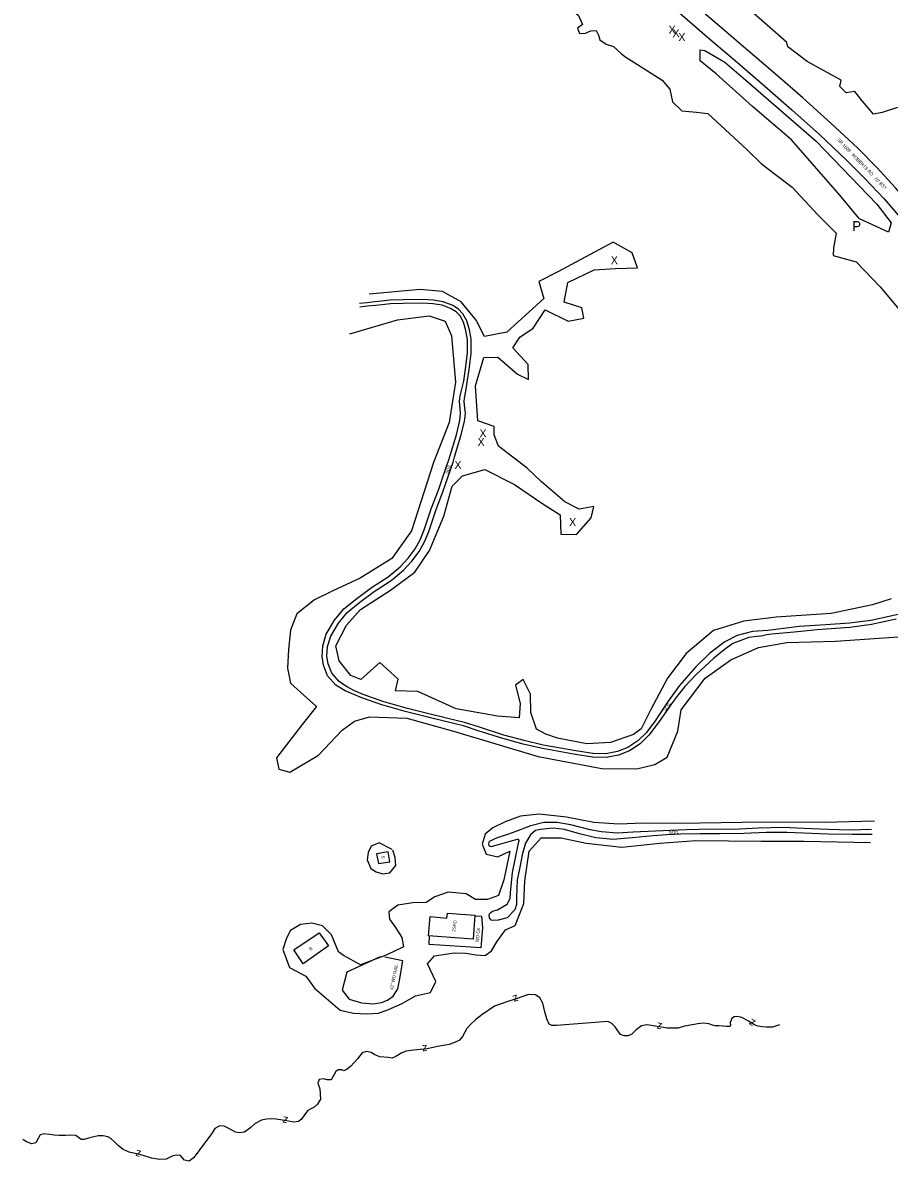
# Model space of a CAD drawing. Extents: x 2030130 to 2036320, y 723205 to 762423.
# Drawn here: x 2032607 to 2033690, y 732880 to 734303 of the extents above; entities that cross this region are included whole.
import ezdxf

# ---------------------------------------------------------------- set-up
doc = ezdxf.new("R2010")
doc.units = 0
for name, color, linetype in [('Draft_Station Labels Major', 7, 'Continuous'), ('Draft_Station Tics Major', 7, 'Continuous'), ('Exist Terrain Model Ground Surface', 7, 'Continuous'), ('Old_Level_23', 7, 'Continuous'), ('Old_Level_28', 7, 'Continuous'), ('Prop Alignment Horizontal', 7, 'Continuous'), ('Prop Horizontal Alignment Ramp', 7, 'Continuous')]:
    doc.layers.add(name, color=color, linetype=linetype)

msp = doc.modelspace()

# ---------------------------------------------------------------- linework, layer by layer
at = {"layer": 'Draft_Station Labels Major'}
for points in [[(2033650.8, 734146.7), (2033617.2, 734178), (2033582.2, 734209.3), (2033547.5, 734239.3), (2033513.4, 734268.8), (2033478.5, 734298.7), (2033443.8, 734328.4), (2033408, 734359), (2033373, 734389), (2033337.5, 734419.8)], [(2033323.5, 734405.1), (2033360.4, 734373.3), (2033395.1, 734343.7), (2033431.2, 734313), (2033465.6, 734283.4), (2033500.4, 734253.6), (2033534.6, 734224), (2033568.5, 734194.3), (2033602.8, 734163.7), (2033636.3, 734131.9), (2033659.9, 734108.3), (2033683.5, 734083.1), (2033706.2, 734056.8), (2033727.1, 734030.7), (2033748, 734002.9), (2033774.8, 733965.5)], [(2033792, 733977), (2033764.1, 734015.1), (2033743.3, 734042.9), (2033721.2, 734070.2), (2033698, 734097), (2033674.5, 734122.4), (2033650.8, 734146.7)], [(2033527.4, 733536.8), (2033514.4, 733535.1), (2033494.8, 733527.4), (2033483.6, 733519.7), (2033470.6, 733508.8), (2033449, 733489), (2033434.8, 733473.7), (2033426.1, 733463.4), (2033418.8, 733453.3), (2033404.5, 733432.7), (2033390.2, 733413.2), (2033378.6, 733402.2), (2033365.4, 733393.3), (2033351.9, 733387.9), (2033336.4, 733385.1), (2033319.1, 733385.4), (2033297.8, 733388.7), (2033256.9, 733396.1), (2033232.6, 733401.6), (2033207.2, 733408.6), (2033176.5, 733418.4), (2033158.2, 733424.5), (2033137.4, 733429.5), (2033111.9, 733435.7), (2033085.2, 733442.3), (2033055.9, 733450.6), (2033031.1, 733459.6), (2033010.3, 733468.1), (2032998.6, 733475.3), (2032988.3, 733487.1), (2032983, 733500.5), (2032981.3, 733511.2), (2032982.1, 733524.7), (2032986.6, 733539), (2032997, 733556.4), (2033008.5, 733570.6), (2033024.8, 733583.6), (2033043.1, 733597.4), (2033064, 733610.8), (2033079.1, 733623.2), (2033088.8, 733634), (2033097.8, 733645.8), (2033104.1, 733656.9), (2033109, 733669.6), (2033117.7, 733695.9), (2033127.2, 733720.3), (2033135.7, 733745.3), (2033139.3, 733755.7), (2033141.2, 733762.4), (2033149.1, 733788.3), (2033153.4, 733806), (2033154.4, 733815.1), (2033153.8, 733821.2), (2033152.9, 733829.8), (2033153.7, 733836.8), (2033158.4, 733855.4), (2033160.7, 733870.6), (2033163.1, 733890.4), (2033163.1, 733907.5), (2033161.1, 733918.5), (2033158, 733929.1), (2033153.7, 733936.8), (2033148.7, 733942.1), (2033141.7, 733946.2), (2033131.3, 733950.2), (2033119.8, 733951.9), (2033106.7, 733952.7), (2033082.7, 733952.3), (2033066.7, 733952), (2033055.9, 733950.8), (2033047.9, 733949.9), (2033038.2, 733948.9), (2033028.5, 733947.9)], [(2033163.1, 733856.4), (2033165.2, 733870), (2033167.7, 733890.1), (2033167.6, 733907.9), (2033165.5, 733919.5), (2033162.2, 733930.9), (2033157.4, 733939.5), (2033151.5, 733945.6), (2033143.7, 733950.3), (2033132.5, 733954.6), (2033120.2, 733956.4), (2033106.8, 733957.3), (2033082.6, 733956.8), (2033066.4, 733956.6), (2033055.4, 733955.3), (2033047.4, 733954.4), (2033037.7, 733953.4), (2033028.1, 733952.4)], [(2033159.4, 733834.1), (2033160.8, 733842.8), (2033163.1, 733856.4)], [(2033006.2, 733477.6), (2033002.5, 733479.9), (2032993.4, 733490.3), (2032988.8, 733502.1), (2032987.3, 733511.5), (2032988, 733523.6), (2032992.1, 733536.6), (2033001.9, 733553), (2033012.7, 733566.3), (2033028.4, 733578.9), (2033046.4, 733592.5), (2033067.5, 733606), (2033083.2, 733618.9), (2033093.4, 733630.2), (2033102.8, 733642.6), (2033109.4, 733654.4), (2033114.6, 733667.6), (2033123.3, 733693.8), (2033132.8, 733718.2), (2033141.4, 733743.3), (2033145, 733753.9), (2033146.9, 733760.7), (2033154.9, 733786.8), (2033159.3, 733805), (2033160.4, 733815.1), (2033159.7, 733821.9), (2033158.8, 733829.8), (2033159.4, 733834.1)], [(2033864.6, 733659.4), (2033863.4, 733657.5), (2033854.4, 733640.7), (2033846.8, 733627), (2033838.9, 733616.5), (2033833.7, 733610.4), (2033826.8, 733604.5), (2033817, 733597.9), (2033808.2, 733593.3), (2033797.5, 733588.6), (2033783.9, 733583.8), (2033768.2, 733579.3), (2033750.9, 733574.4), (2033728.7, 733569.8), (2033697.5, 733562.9), (2033667, 733556.3), (2033640.2, 733552.7), (2033610.7, 733550.6)], [(2033610.7, 733550.6), (2033577.3, 733548.5), (2033538.2, 733543.8), (2033519.1, 733542.3), (2033500, 733537.3), (2033484.5, 733529.5), (2033466, 733515.4), (2033448.2, 733498.3), (2033428, 733474.8), (2033413.7, 733455.5), (2033397.4, 733430.7)], [(2033698.7, 733557.7), (2033667.9, 733551.1), (2033640.7, 733547.3), (2033599.8, 733544.5), (2033571.1, 733541.8), (2033543.3, 733538.9), (2033534.3, 733537.7)], [(2033527.4, 733536.8), (2033534.3, 733537.7)], [(2033021.2, 733468.5), (2033012.7, 733473.2), (2033006.2, 733477.6)], [(2033397.4, 733430.7), (2033386.8, 733416.2), (2033375.8, 733405.7), (2033363.3, 733397.3), (2033350.6, 733392.3), (2033336, 733389.6), (2033319.5, 733390), (2033298.5, 733393.2), (2033257.8, 733400.5), (2033233.7, 733406), (2033208.5, 733413), (2033177.9, 733422.7), (2033159.4, 733428.9), (2033138.5, 733433.9), (2033113, 733440.1), (2033086.3, 733446.6), (2033057.3, 733454.9), (2033032.7, 733463.8), (2033021.2, 733468.5)], [(2033200.7, 733194.5), (2033212.6, 733201.6), (2033216.4, 733208.9), (2033216.7, 733215.8), (2033219.4, 733241.4), (2033223.3, 733261.8), (2033226.5, 733275.9), (2033227.7, 733281), (2033226.9, 733282.3), (2033225.3, 733282.4), (2033215.9, 733280.1), (2033201.4, 733275.6), (2033192.3, 733273.1), (2033190, 733274.4), (2033189.5, 733277), (2033190.5, 733280.3), (2033200.6, 733284.8), (2033214.7, 733289.6), (2033227, 733294.1), (2033242.3, 733299.8), (2033258.5, 733304.2), (2033275.1, 733304.2), (2033291.6, 733301.3), (2033315.9, 733294.9), (2033330.4, 733292.3), (2033350, 733290.8), (2033370.2, 733291.9), (2033416.8, 733294.2), (2033436.5, 733295.1), (2033466.7, 733295.6), (2033495.1, 733295.5), (2033526.8, 733297.2), (2033557.6, 733297.8), (2033583.4, 733296.7), (2033614.2, 733295.5), (2033640.8, 733294.7), (2033667.9, 733295.5)], [(2033668.9, 733288.8), (2033644.2, 733288.8), (2033613.8, 733289), (2033582.7, 733290.3), (2033562.2, 733291.2), (2033536.3, 733291), (2033508.2, 733290.1), (2033478.3, 733289.7), (2033453.2, 733289.5), (2033429.7, 733289.3), (2033412.1, 733288.2), (2033395, 733287.1), (2033368.9, 733284.7), (2033344.7, 733282.6), (2033332.6, 733283.5), (2033323.3, 733284.7), (2033303, 733289.7), (2033284.1, 733294.8), (2033270.3, 733296.7), (2033254.1, 733295.1), (2033248.1, 733293.5), (2033241.9, 733288.1), (2033235.7, 733277.8), (2033231.5, 733263.2), (2033229.2, 733251.9), (2033225.2, 733231.7), (2033224.3, 733209.9), (2033224.4, 733201.2), (2033222.3, 733194.6), (2033212.7, 733184.7), (2033201.5, 733181.8)], [(2033201.5, 733181.8), (2033194.7, 733181.1), (2033192.7, 733181.8), (2033190.7, 733184.6), (2033190.1, 733187.5), (2033190.4, 733189.7), (2033192.1, 733191.4), (2033194.4, 733192.8), (2033200.7, 733194.5)]]:
    msp.add_lwpolyline(points, dxfattribs=at)
at = {"layer": 'Draft_Station Tics Major'}
msp.add_line((2033688.9, 734041.6), (2033653, 734058.3), dxfattribs=at)
for points in [[(2033224.4, 734382.4), (2033241.5, 734365.7), (2033248, 734361.9), (2033251.5, 734355.1), (2033255.6, 734348.1), (2033270, 734335), (2033277.5, 734331.8), (2033285.7, 734323.9), (2033294.9, 734318.4), (2033301.7, 734312.4), (2033306.6, 734301.2), (2033300.7, 734296.6), (2033302.9, 734290), (2033310.5, 734290.1), (2033317.2, 734293.2), (2033323.7, 734293.7), (2033326.7, 734287.7), (2033328.3, 734281.8), (2033336.2, 734276.5), (2033345.6, 734273.5), (2033354.9, 734264.9), (2033359.7, 734261.1)], [(2033587.5, 734254.7), (2033563.3, 734273.4), (2033562, 734278.7), (2033537.5, 734300.2), (2033504.3, 734329.5)], [(2033652.4, 734058.6), (2033628.4, 734087.8), (2033568, 734157), (2033519.1, 734198.8), (2033473.6, 734239.5), (2033453.8, 734255.6), (2033453.9, 734269.4), (2033459.7, 734268.7), (2033484.5, 734253.9)], [(2033359.7, 734261.1), (2033387.8, 734243.4), (2033406.5, 734231.7), (2033415.7, 734220.2), (2033419.4, 734204.6), (2033430.7, 734193.1), (2033449.4, 734191.4), (2033463.5, 734189.9), (2033512.3, 734144.4), (2033530.5, 734127), (2033568.7, 734097.7), (2033600.9, 734063.2), (2033623.7, 734040.4), (2033620.7, 734024)], [(2033484.5, 734253.9), (2033510.8, 734231.4), (2033598.9, 734155.5), (2033674.5, 734076.5), (2033692.4, 734053.2), (2033689.2, 734041.5)], [(2033752.6, 734248.1), (2033762.2, 734231.6), (2033757, 734222.9), (2033743.5, 734213.8), (2033718, 734201.4), (2033697.9, 734196.5), (2033681.3, 734191.3), (2033670.5, 734188.9), (2033656.3, 734205.9), (2033647.2, 734217.6), (2033636.2, 734215.6), (2033628.5, 734223.5), (2033629.9, 734231.7), (2033587.5, 734254.7)], [(2033692.3, 733583.2), (2033669, 733575.6), (2033617.3, 733565), (2033548.7, 733560.3), (2033508.3, 733555.5), (2033470.4, 733543.8), (2033436.4, 733515.1), (2033413, 733484.1), (2033392.3, 733444.8), (2033380.1, 733420.7), (2033370.6, 733413.7), (2033341.8, 733403.7), (2033312, 733402.1), (2033275.6, 733409), (2033260.8, 733414.1), (2033249.3, 733420.5), (2033242, 733441.4), (2033241.7, 733464.3), (2033232.4, 733482.5), (2033223.1, 733475.4), (2033228.8, 733452.6), (2033227.7, 733434.5), (2033200.6, 733436.7), (2033148.7, 733445.7), (2033100.9, 733467.3), (2033073.1, 733468.2), (2033076.6, 733482.8), (2033053.6, 733503.6), (2033029.7, 733482.4), (2033017.2, 733487.5), (2033002.5, 733505.7), (2032998.7, 733524.4), (2033012, 733550.4), (2033029.2, 733570), (2033067, 733594), (2033097.4, 733616.8), (2033115.4, 733643.8), (2033133.6, 733686.6), (2033143.8, 733724.1), (2033156.9, 733737.1), (2033184.9, 733744.9), (2033221.9, 733726.2), (2033257.2, 733702.1), (2033278.8, 733688.4), (2033279.7, 733664.2), (2033299.2, 733663.7), (2033317.6, 733684.5), (2033320.9, 733698.6), (2033302.5, 733695.4), (2033284.7, 733704.5), (2033255.6, 733729.5), (2033237.5, 733746.5), (2033201.6, 733773.9), (2033196.4, 733788.2), (2033196.3, 733798.5), (2033176.1, 733805.7), (2033173, 733849.5), (2033183.6, 733885.1), (2033201.1, 733885.2), (2033225.4, 733864.2), (2033239.2, 733857.3), (2033239, 733876.2), (2033219.9, 733897.1), (2033228.6, 733910.4), (2033244.9, 733921.5), (2033260, 733944.3), (2033288.7, 733930.4), (2033308.6, 733934.2), (2033305.8, 733946.9), (2033283.9, 733953.9), (2033288.4, 733978.7), (2033321.3, 733994.3), (2033348, 733996.2), (2033375.4, 733997.2), (2033368.6, 734015.8), (2033345, 734029), (2033276.1, 733992.1), (2033252.3, 733980.1), (2033258.5, 733958.8), (2033212, 733916.7)], [(2033620.7, 734024), (2033620.4, 734022.1), (2033620.1, 734012.4), (2033648.9, 734004.5), (2033678.9, 733973.2)], [(2033212, 733916.7), (2033184.3, 733911.2), (2033173.8, 733931.4), (2033155.2, 733954.7), (2033131.7, 733967.6), (2033103.9, 733970), (2033040, 733964.2)], [(2033678.9, 733973.2), (2033736, 733904.6)], [(2033016, 733914.7), (2033075.4, 733931.9), (2033115.3, 733937.2), (2033135, 733930.4), (2033143.1, 733912.2), (2033148, 733854), (2033140.2, 733803.7), (2033120.6, 733753.5), (2033092.9, 733668.1), (2033068.3, 733633.8), (2033029, 733609.3), (2032994.6, 733593.4), (2032972, 733582), (2032949.7, 733564.4), (2032941.9, 733543.9), (2032939.4, 733519.9), (2032938, 733496.6), (2032941.8, 733477.7), (2032954.7, 733466.1), (2032974.5, 733448.8), (2032956.4, 733426.2), (2032924.4, 733384.5), (2032927.5, 733370.5), (2032940.9, 733366.8), (2032977, 733387.8), (2033006.3, 733419.3), (2033022, 733430.2), (2033040.4, 733435.6), (2033087.1, 733434.1), (2033145.6, 733417.9), (2033251.4, 733386.3), (2033330.7, 733371.2), (2033374.5, 733370.9), (2033397.3, 733376), (2033412.7, 733385.3), (2033425.9, 733418), (2033429.9, 733444.5), (2033460, 733484), (2033492.1, 733507), (2033526.5, 733522.6), (2033562, 733528.6), (2033622.8, 733530.5), (2033701.8, 733535.9)], [(2033671.7, 733305.5), (2033608.8, 733303.5), (2033532.8, 733304.3), (2033426.5, 733302.6), (2033383, 733302.7), (2033352.2, 733301.5), (2033321.1, 733303.7), (2033286.6, 733310.4), (2033252.5, 733314.1), (2033229.1, 733311.7), (2033210.2, 733304.4), (2033194.5, 733296.9), (2033185.1, 733289), (2033181.4, 733276.6), (2033186.2, 733264.1), (2033200.9, 733260.6), (2033216, 733268), (2033208.6, 733232.1), (2033201.9, 733212.5), (2033188.1, 733207.5), (2033173.2, 733207.5), (2033161.3, 733214.4), (2033138.8, 733216.6), (2033122.1, 733210.6), (2033111.4, 733203.7)], [(2033199.7, 733154.5), (2033210.7, 733169.4), (2033222.6, 733175), (2033233.6, 733202.6), (2033234.8, 733230.6), (2033240.3, 733267.9), (2033255.1, 733284.5), (2033279.9, 733284.5), (2033311.2, 733277.9), (2033355.7, 733273), (2033403.5, 733277.9), (2033448.2, 733281.1), (2033530.1, 733280.5), (2033583.7, 733280.5), (2033666.5, 733278.5)], [(2033069, 733269.9), (2033052.8, 733278.2), (2033042.8, 733274), (2033038.9, 733266.1), (2033037.8, 733257), (2033042.2, 733246.1), (2033048.8, 733242), (2033057.3, 733239.7), (2033066.2, 733240.9), (2033073.3, 733249.8), (2033072.5, 733260), (2033069.9, 733269)], [(2033111.4, 733203.7), (2033094.6, 733203.5), (2033076, 733200.5), (2033064.7, 733191.9), (2033065.6, 733182.9), (2033073, 733172.5), (2033081, 733159.8), (2033082.9, 733148.1), (2033061.5, 733137.9), (2033029.4, 733125.6), (2033007.9, 733137.6), (2033001.9, 733142.2), (2032993, 733163.1), (2032981.9, 733174.6), (2032968.7, 733177.7), (2032954.4, 733176.4), (2032941.9, 733168.6), (2032936.9, 733159.1), (2032932.1, 733145), (2032940.7, 733122.6), (2032961.2, 733111.7), (2032972, 733096.5), (2033003.9, 733069.3), (2033020.4, 733065.2), (2033037.3, 733064.5), (2033051.7, 733065.4), (2033064.2, 733069.9), (2033081.3, 733077.3), (2033098.2, 733087.2), (2033116.9, 733091.2), (2033123.3, 733104.8), (2033113, 733127), (2033122, 733137.2), (2033146.3, 733140.6), (2033161, 733140.5), (2033173.5, 733138.4), (2033185.2, 733137.5), (2033193.1, 733143.3), (2033199.7, 733154.5)]]:
    msp.add_lwpolyline(points, dxfattribs=at)
at = {"layer": 'Exist Terrain Model Ground Surface'}
for points in [[(2033064, 733267), (2033049.5, 733264.4), (2033051.8, 733252.4), (2033066.2, 733254.6)], [(2033170, 733157.9), (2033114.3, 733162.2), (2033116.5, 733186.3), (2033137.4, 733184), (2033137.9, 733190.4), (2033172.2, 733187.9)], [(2032989.2, 733149.6), (2032957.8, 733127), (2032946.2, 733144.5), (2032977.7, 733165.9)]]:
    msp.add_lwpolyline(points, close=True, dxfattribs=at)
for points in [[(2033172.1, 733187.2), (2033180.4, 733186.7), (2033181.9, 733172.2), (2033179.8, 733147.1), (2033115, 733151.4), (2033115.7, 733162.1)], [(2033053.8, 733135.9), (2033012.3, 733116.8), (2033006.3, 733094.1), (2033015.1, 733083), (2033030.7, 733078.3), (2033045.4, 733077.1), (2033055.4, 733078.9), (2033063.1, 733081.5), (2033070, 733086.8), (2033076.1, 733095.7), (2033078, 733106.4), (2033082.2, 733130.9), (2033059.8, 733135.5)]]:
    msp.add_lwpolyline(points, dxfattribs=at)
at = {"layer": 'Prop Alignment Horizontal'}
for points in [[(2033553, 733050.7), (2033544.1, 733047.8), (2033536.3, 733047.9), (2033531.1, 733048.2), (2033525.9, 733049), (2033521.8, 733050.8), (2033514, 733055.4), (2033508.5, 733058.8), (2033504.4, 733060.5), (2033499.2, 733061.2), (2033496.2, 733061), (2033493.3, 733058.6), (2033491.2, 733053.9), (2033491.8, 733050.5), (2033490.4, 733048.9), (2033486.1, 733048.9), (2033476.9, 733049.6), (2033472.7, 733049.5), (2033469.3, 733050.2), (2033464.7, 733052.2), (2033457.7, 733052.7), (2033451, 733052.2), (2033446.2, 733051.4), (2033434.1, 733049.3), (2033426.2, 733046.7), (2033412.9, 733046.7), (2033387.6, 733050.9), (2033380.3, 733049.7), (2033373.9, 733044.6), (2033368.3, 733039), (2033363.9, 733037.2), (2033359, 733037.1), (2033354.1, 733038.9), (2033350.2, 733044.4), (2033347.6, 733048.5), (2033343.3, 733052.4), (2033338.4, 733054.8), (2033274.4, 733050.1), (2033268.6, 733049.8), (2033264.9, 733051.7), (2033262.3, 733058.3), (2033259.7, 733067), (2033257.1, 733077.8), (2033253.6, 733084.6), (2033247.9, 733088.3), (2033239.4, 733088.6), (2033224, 733083.2), (2033212.3, 733079.6), (2033196.8, 733074.1), (2033181.1, 733063.5), (2033173.5, 733057.4), (2033167.4, 733051.7), (2033162.3, 733046.2), (2033159.8, 733041.8), (2033157, 733036.4), (2033153.1, 733031.5), (2033146, 733028.2), (2033140.1, 733026.3), (2033135.5, 733025.4), (2033125.7, 733023.6), (2033112.7, 733020.9), (2033104.1, 733020), (2033095.5, 733019.1), (2033086.3, 733017.7), (2033081.1, 733015.6), (2033073.5, 733011.1), (2033068.8, 733009), (2033063.8, 733009.8), (2033053.3, 733010.8), (2033047.2, 733013.1), (2033042.8, 733016.1), (2033036.9, 733017.6), (2033031.5, 733015.9), (2033025.7, 733008.1), (2033017.4, 732999.2), (2033012.7, 732995.4), (2033008.6, 732993.4), (2033006, 732994.6), (2033001.3, 732994.7), (2032998.4, 732992.4), (2032992.9, 732982), (2032987.6, 732982), (2032983, 732983.4), (2032977.5, 732982.5), (2032975.9, 732977.9), (2032978.4, 732971), (2032979.3, 732957.9), (2032975.5, 732951.5), (2032971.5, 732947.8), (2032967.3, 732945.9), (2032963.7, 732943.9), (2032959.2, 732938.3), (2032955.8, 732932.9), (2032951.7, 732929.9), (2032946.1, 732929.1), (2032937.2, 732930.7), (2032931.7, 732931.8), (2032923.8, 732933.1), (2032917.7, 732933.2), (2032912, 732933.1), (2032905.5, 732931.7)], [(2032905.5, 732931.7), (2032897.6, 732927.5), (2032892.4, 732922.6), (2032884.2, 732916.7), (2032878, 732915.9), (2032873.3, 732916.8), (2032864.8, 732921.1), (2032859.1, 732924.1), (2032853.5, 732924.4), (2032847.5, 732921.1), (2032843.5, 732914.9), (2032830.5, 732897.9), (2032825.1, 732890.5), (2032820.7, 732884.7), (2032815.1, 732880.3), (2032809.4, 732881.7), (2032804.5, 732887.3), (2032799.2, 732887.9), (2032794, 732886.6), (2032786.5, 732883.1), (2032778.1, 732882.3), (2032768, 732884.3), (2032757.9, 732887.3), (2032753.3, 732888.7), (2032740.2, 732891.6), (2032732.7, 732894.9), (2032726.8, 732899.6), (2032721.4, 732905.1), (2032717.2, 732908.9), (2032713.7, 732910.9), (2032707.7, 732912.1), (2032701.6, 732912.2), (2032694.4, 732910.5), (2032689.6, 732909.1), (2032684, 732907.3), (2032680.3, 732907.4), (2032677.1, 732909.8), (2032673.7, 732912.4), (2032667.5, 732912.8), (2032660.6, 732912.4), (2032653, 732912.6), (2032646.6, 732913.1), (2032640.7, 732913.9), (2032634.7, 732914.7), (2032629.2, 732913.3), (2032623.8, 732903.4), (2032618.8, 732901.9), (2032612.1, 732904.4), (2032608.5, 732906.8), (2032607.4, 732907.8)]]:
    msp.add_lwpolyline(points, dxfattribs=at)

# ---------------------------------------------------------------- texts
at = {"layer": 'Draft_Station Tics Major'}
for p in [(2033414.3, 734289.7), (2033419.2, 734285.3), (2033426.5, 734280.4), (2033342.1, 734001.5), (2033178, 733785.2), (2033175.6, 733774.3), (2033146.7, 733745.7), (2033290, 733674.1)]:
    msp.add_text('X', height=10, dxfattribs=at).set_placement(p)
at = {"layer": 'Old_Level_23'}
for s, rotation, p in [("SR 1608   ROBERTS RD   20' BST", 314.0766, (2033624.6, 734156.4)), ('SOIL', 70.7784, (2033138.8, 733738.9)), ('SOIL', 55.646, (2033410.4, 733442.3)), ('SOIL', 3.8637, (2033414.8, 733289.1))]:
    msp.add_text(s, height=4, rotation=rotation, dxfattribs=at).set_placement(p)
at = {"layer": 'Old_Level_28'}
for s, rotation, p in [('S', 95.5671, (2033059.9, 733258.7)), ('2SFD', 83.4758, (2033147.9, 733167.1)), ('WD DK', 84.1671, (2033177, 733153.9)), ('B', 33.3508, (2032966.8, 733143.3)), ('42" WD RAIL', 78.745, (2033070, 733094.1))]:
    msp.add_text(s, height=4, rotation=rotation, dxfattribs=at).set_placement(p)
at = {"layer": 'Prop Alignment Horizontal'}
for rotation, p in [(198.2017, (2033224.9, 733088.8)), (170.6734, (2033406.7, 733052.8)), (148.5777, (2033523.6, 733055.4)), (185.8229, (2033112.5, 733025.9)), (169.692, (2032939.3, 732935.3)), (166.0052, (2032755.8, 732893.1))]:
    msp.add_text('z', height=10, rotation=rotation, dxfattribs=at).set_placement(p)
at = {"layer": 'Prop Horizontal Alignment Ramp'}
msp.add_text('P', height=12.5, dxfattribs=at).set_placement((2033643.7, 734042.9))

doc.saveas('drawing.dxf')
